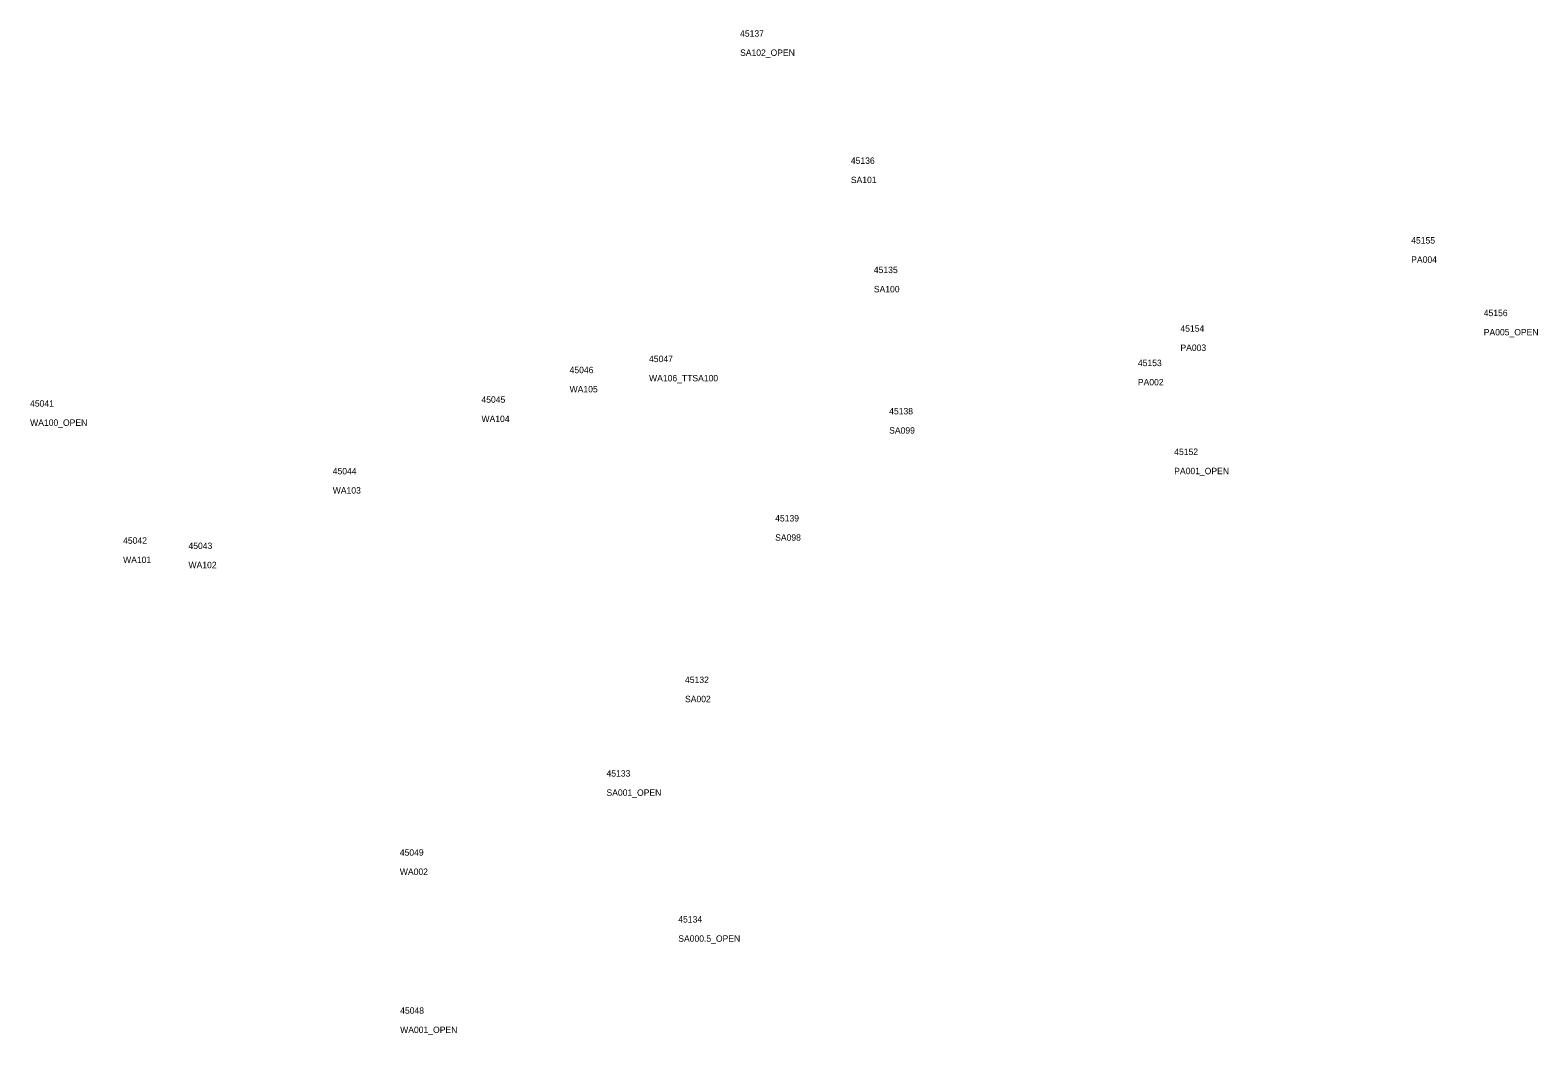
# Model space of a CAD drawing. Extents: x 1503676 to 1665494, y 654328 to 989038.
# Drawn here: x 1637455 to 1638043, y 763371 to 763763 of the extents above; entities that cross this region are included whole.
import ezdxf

# ---------------------------------------------------------------- set-up
doc = ezdxf.new("R2010")
doc.units = 0
for name, color, linetype in [('Level 14', 7, 'Continuous'), ('Level 17', 7, 'Continuous'), ('Level 18', 7, 'Continuous'), ('Level 19', 7, 'Continuous'), ('Level 21', 7, 'Continuous'), ('Level 22', 7, 'Continuous')]:
    doc.layers.add(name, color=color, linetype=linetype)

msp = doc.modelspace()

# ---------------------------------------------------------------- texts
at = {"layer": 'Level 14'}
for s, p in [('45047', (1637696.23, 763633.68)), ('45046', (1637665.25, 763629.37)), ('45041', (1637454.86, 763616.32)), ('45045', (1637630.88, 763617.81)), ('45044', (1637572.88, 763589.91)), ('45042', (1637491.13, 763562.81)), ('45043', (1637516.63, 763560.79)), ('45049', (1637599.04, 763441.15)), ('45048', (1637599.17, 763379.47))]:
    msp.add_text(s, height=2.5, dxfattribs=at).set_placement(p)
at = {"layer": 'Level 17'}
for s, p in [('WA106_TTSA100', (1637696.23, 763626.18)), ('WA105', (1637665.25, 763621.87)), ('WA100_OPEN', (1637454.86, 763608.82)), ('WA104', (1637630.88, 763610.31)), ('WA103', (1637572.88, 763582.41)), ('WA101', (1637491.13, 763555.31)), ('WA102', (1637516.63, 763553.29)), ('WA002', (1637599.04, 763433.65)), ('WA001_OPEN', (1637599.17, 763371.97))]:
    msp.add_text(s, height=2.5, dxfattribs=at).set_placement(p)
at = {"layer": 'Level 18'}
for s, p in [('SA102_OPEN', (1637731.73, 763753.14)), ('SA101', (1637774.93, 763703.52)), ('SA100', (1637783.89, 763660.91)), ('SA099', (1637789.87, 763605.8)), ('SA098', (1637745.41, 763564.01)), ('SA002', (1637710.26, 763501.01)), ('SA001_OPEN', (1637679.64, 763464.5)), ('SA000.5_OPEN', (1637707.63, 763407.57))]:
    msp.add_text(s, height=2.5, dxfattribs=at).set_placement(p)
at = {"layer": 'Level 19'}
for s, p in [('45137', (1637731.73, 763760.64)), ('45136', (1637774.93, 763711.02)), ('45135', (1637783.89, 763668.41)), ('45138', (1637789.87, 763613.3)), ('45139', (1637745.41, 763571.51)), ('45132', (1637710.26, 763508.51)), ('45133', (1637679.64, 763472)), ('45134', (1637707.63, 763415.07))]:
    msp.add_text(s, height=2.5, dxfattribs=at).set_placement(p)
at = {"layer": 'Level 21'}
for s, p in [('PA004', (1637993.45, 763672.43)), ('PA005_OPEN', (1638021.74, 763644.11)), ('PA003', (1637903.45, 763638.05)), ('PA002', (1637886.86, 763624.61)), ('PA001_OPEN', (1637901.03, 763589.96))]:
    msp.add_text(s, height=2.5, dxfattribs=at).set_placement(p)
at = {"layer": 'Level 22'}
for s, p in [('45155', (1637993.45, 763679.93)), ('45156', (1638021.74, 763651.61)), ('45154', (1637903.45, 763645.55)), ('45153', (1637886.86, 763632.11)), ('45152', (1637901.03, 763597.46))]:
    msp.add_text(s, height=2.5, dxfattribs=at).set_placement(p)

doc.saveas('drawing.dxf')
